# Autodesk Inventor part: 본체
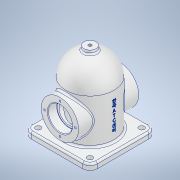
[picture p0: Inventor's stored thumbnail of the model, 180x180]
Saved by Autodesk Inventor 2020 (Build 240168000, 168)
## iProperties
Created: 2021-07
Part Number: 본체
Material: 알루미늄 6061
Document SubType Name: Modeling
Designer: Owner
Density: 2.7 g/cm^3
Appearance: 알루미늄 - 평지
Mass: 865.906 g
Surface Area: 800.755 cm^2
Volume: 320.706 cm^3
Author: Owner
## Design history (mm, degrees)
sketch "스케치1"
  geometry: C1 r 40 at (0, 0); 1 further point
  constraints: 1 centre point, 1 coincident
  dimensions: "d0" = 80 diameter of C1
extrude "돌출1" new body sketch "스케치1" distance "d1" = 124; taper "d2" = 0 deg
sketch "스케치2"
  geometry: 1 further point
fillet "모깎기1" dims "d3" = 40
feature "쉘1" dims "d4" = 8
sketch "스케치3"
  geometry: L1 (-55, 55)-(55, 55); L2 (55, 55)-(55, -55); L3 (55, -55)-(-55, -55); L4 (-55, -55)-(-55, 55); L5 (-55, 55)-(55, -55); L6 (55, 55)-(-55, -55); C1 r 32 at (0, 0) reference; 1 further point
  constraints: 12 end point, 2 midpoint, 2 parallel, 1 horizontal, 1 perpendicular
  dimensions: "d5" = 110 distance of L2.end L3.end; "d6" = 110 distance of L1.end L2.end
extrude "돌출2" join sketch "스케치3" distance "d7" = 10; taper "d8" = 0 deg
fillet "모깎기2" dims "d9" = 12
fillet "모깎기3" dims "d10" = 3
sketch "스케치4"
  geometry: A1 r 9 centre (-43, 43) between (-43, 52) and (-52, 43) reference; A2 r 9 centre (43, 43) between (52, 43) and (43, 52) reference; A3 r 12 centre (43, -43) between (43, -55) and (55, -43) reference; A4 r 12 centre (-43, -43) between (-55, -43) and (-43, -55) reference; 5 further points
  constraints: 4 coincident
hole "구멍1" sketch "스케치4" at (-43, -43), (43, -43), (43, 43), (-43, 43) diameter "d11" = 9; stored, may be unused: countersink angle "d15" = 90 deg, drill point angle "d17" = 0 deg; dims "d12" = 6, "d13" = 4, "d14" = 2, "d16" = 8
node "작업 평면1"
sketch "스케치5"
  geometry: L1 (-43, 0)-(43, 0) reference; C1 r 31 at (0, 48); 2 further points
  constraints: 1 centre point, 1 midpoint, 1 vertical alignment
  dimensions: "d19" = 62 diameter of C1; "d20" = 48 distance from line of L1 C1.centre
extrude "돌출3" join sketch "스케치5" stored distance "d21" = 10; taper "d22" = 0 deg
sketch "스케치6"
  geometry: C1 r 31 at (0, 0) reference; 2 further points
  constraints: 1 coincident
hole "구멍2" sketch "스케치6" at (0, 0) diameter "d23" = 33; stored, may be unused: countersink angle "d27" = 90 deg, drill point angle "d29" = 0 deg; dims "d24" = 6, "d25" = 40, "d26" = 15, "d28" = 8
sketch "스케치7"
  geometry: C1 r 31 at (0, 0) reference; A1 r 25.5 centre (0, 0) between (0, 25.5) and (-25.5, 0); 3 further points
  constraints: 4 point on circle, 2 horizontal alignment, 2 vertical alignment, 1 centre point, 1 coincident
  dimensions: "d30" = 51 diameter of A1
hole "구멍3" sketch "스케치7" at (0, 25.5), (-25.5, 0), (25.5, 0), (0, -25.5) diameter "d31" = 3.242; stored, may be unused: countersink angle "d35" = 90 deg, drill point angle "d37" = 118 deg; dims "d32" = 8, "d33" = 40, "d34" = 15, "d36" = 10
fillet "모깎기4" dims "d38" = 3
node "작업 평면2"
sketch "스케치8"
  geometry: C1 r 10 at (0, 0); 1 further point
  constraints: 1 centre point, 1 coincident
  dimensions: "d40" = 20 diameter of C1
extrude "돌출4" join sketch "스케치8" stored distance "d41" = 10; taper "d42" = 0 deg
sketch "스케치9"
  geometry: C1 r 10 at (0, 0) reference; 2 further points
  constraints: 1 coincident
hole "구멍4" sketch "스케치9" at (0, 0) diameter "d43" = 5.1881; stored, may be unused: countersink angle "d47" = 90 deg, drill point angle "d49" = 0 deg; dims "d44" = 12, "d45" = 40, "d46" = 15, "d48" = 16
fillet "모깎기5" dims "d50" = 3
node "작업 평면3"
sketch "스케치10"
  geometry: L1 (0, 43)-(0, -43) reference; 3 further points
  constraints: 1 horizontal alignment, 1 midpoint, 1 other
  dimensions: "d51" = 48 distance from line of L1 point (48, 0)
feature "엠보싱1" sketch "스케치10" dims "d1" = 124, "d2" = 0, "d9" = 12, "d52" = 0.5, "d53" = 0
chamfer "모따기1" distance "d54" = 1; stored, may be unused: second distance "d55" = 2, angle "d56" = 45 deg
chamfer "모따기2" distance "d57" = 1; stored, may be unused: second distance "d58" = 2, angle "d59" = 45 deg
fillet "모깎기6" dims "d60" = 0.3
node "솔리드1"
mirror "미러1"
mirror "미러2"
feature "A9D066F2-1C7D-4E18-AEED-F7BC21143FA4" dims "d23" = 33, "d24" = 6, "d25" = 40, "d26" = 15, "d27" = 90 deg, "d28" = 8, "d29" = 0
other parameters: "d39" = 129
